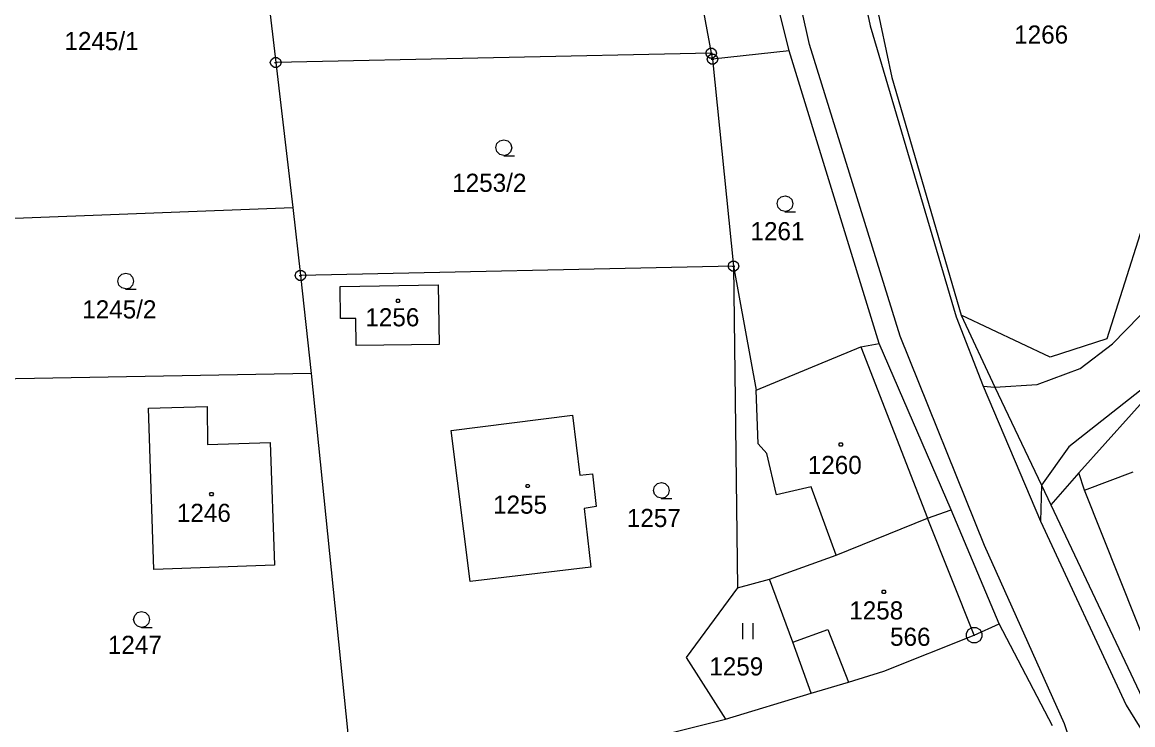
# Model space of a CAD drawing. Extents: x -609861 to -605046, y -1120287 to -1116307.
# Drawn here: x -607182.1 to -607078, y -1118980 to -1118914.2 of the extents above; entities that cross this region are included whole.
import ezdxf

# ---------------------------------------------------------------- set-up
doc = ezdxf.new("R2010")
doc.units = 0
for name, color, linetype in [('Vrstva 1', 7, 'Continuous'), ('Vrstva 2', 7, 'Continuous'), ('Vrstva 3', 7, 'Continuous'), ('Vrstva 4', 7, 'Continuous'), ('Vrstva 5', 7, 'Continuous'), ('Vrstva 8', 7, 'Continuous')]:
    doc.layers.add(name, color=color, linetype=linetype)

msp = doc.modelspace()

# ---------------------------------------------------------------- linework, layer by layer
at = {"layer": 'Vrstva 1'}
for p, q in [((-607055.17, -1118863.8), (-607080.44, -1118943.85)), ((-607109.19, -1118878.4), (-607100.61, -1118919.35)), ((-607124.44, -1118880.49), (-607117.52, -1118917.07)), ((-607161.19, -1118893.61), (-607158.35, -1118917.94)), ((-607110.23, -1118916.83), (-607111.09, -1118913.32)), ((-607117.52, -1118917.07), (-607158.35, -1118917.94)), ((-607117.52, -1118917.07), (-607117.41, -1118917.63)), ((-607110.23, -1118916.83), (-607117.41, -1118917.63)), ((-607101.78, -1118944.28), (-607110.23, -1118916.83)), ((-607158.35, -1118917.94), (-607156.76, -1118931.53)), ((-607117.41, -1118917.63), (-607115.43, -1118937.03)), ((-607100.61, -1118919.35), (-607094.11, -1118941.62)), ((-607188.35, -1118932.73), (-607156.76, -1118931.53)), ((-607156.76, -1118931.53), (-607156.02, -1118937.9)), ((-607115.43, -1118937.03), (-607156.02, -1118937.9)), ((-607115.43, -1118937.03), (-607115.05, -1118967.2)), ((-607115.43, -1118937.03), (-607113.3, -1118948.65)), ((-607156.02, -1118937.9), (-607155.04, -1118947.1)), ((-607152.31, -1118938.95), (-607143.11, -1118938.77)), ((-607152.29, -1118941.95), (-607152.31, -1118938.95)), ((-607143.11, -1118938.77), (-607143.02, -1118944.36)), ((-607150.85, -1118941.93), (-607152.29, -1118941.95)), ((-607150.81, -1118944.48), (-607150.85, -1118941.93)), ((-607085.75, -1118945.56), (-607094.11, -1118941.62)), ((-607094.11, -1118941.62), (-607090.94, -1118948.36)), ((-607143.02, -1118944.36), (-607150.81, -1118944.48)), ((-607103.5, -1118944.58), (-607101.78, -1118944.28)), ((-607095.02, -1118959.89), (-607101.78, -1118944.28)), ((-607080.44, -1118943.85), (-607085.75, -1118945.56)), ((-607071.7, -1118943.74), (-607083.08, -1118956.4)), ((-607113.3, -1118948.65), (-607103.5, -1118944.58)), ((-607155.04, -1118947.1), (-607188.46, -1118947.7)), ((-607155.04, -1118947.1), (-607151.26, -1118984.15)), ((-607090.94, -1118948.36), (-607086.57, -1118957.57)), ((-607170.28, -1118950.35), (-607164.79, -1118950.18)), ((-607169.79, -1118965.48), (-607170.28, -1118950.35)), ((-607164.79, -1118950.18), (-607164.74, -1118953.76)), ((-607141.89, -1118952.43), (-607130.53, -1118951.01)), ((-607130.53, -1118951.01), (-607129.85, -1118956.63)), ((-607140.11, -1118966.61), (-607141.89, -1118952.43)), ((-607164.74, -1118953.76), (-607158.87, -1118953.56)), ((-607158.87, -1118953.56), (-607158.45, -1118965.06)), ((-607129.85, -1118956.63), (-607128.66, -1118956.49)), ((-607128.66, -1118956.49), (-607128.3, -1118959.57)), ((-607083.08, -1118956.4), (-607085.68, -1118959.4)), ((-607082.54, -1118958.04), (-607083.08, -1118956.4)), ((-607082.54, -1118958.04), (-607077.97, -1118956.32)), ((-607086.57, -1118957.57), (-607085.68, -1118959.4)), ((-607075.98, -1118974.5), (-607082.54, -1118958.04)), ((-607128.3, -1118959.57), (-607129.44, -1118959.75)), ((-607129.44, -1118959.75), (-607128.82, -1118965.24)), ((-607097.24, -1118960.65), (-607095.02, -1118959.89)), ((-607090.53, -1118970.56), (-607095.02, -1118959.89)), ((-607085.68, -1118959.4), (-607077.1, -1118977.58)), ((-607105.82, -1118964.13), (-607097.24, -1118960.65)), ((-607112.05, -1118966.38), (-607105.82, -1118964.13)), ((-607158.45, -1118965.06), (-607169.79, -1118965.48)), ((-607128.82, -1118965.24), (-607140.11, -1118966.61)), ((-607115.05, -1118967.2), (-607119.87, -1118973.74)), ((-607115.05, -1118967.2), (-607112.05, -1118966.38)), ((-607109.89, -1118972.29), (-607112.05, -1118966.38)), ((-607092.88, -1118971.63), (-607090.53, -1118970.56)), ((-607085.55, -1118980.13), (-607090.53, -1118970.56)), ((-607108.15, -1118977.08), (-607109.89, -1118972.29)), ((-607101.36, -1118975.02), (-607092.88, -1118971.63)), ((-607119.87, -1118973.74), (-607116.19, -1118979.5)), ((-607104.67, -1118976.04), (-607101.36, -1118975.02)), ((-607108.15, -1118977.08), (-607104.67, -1118976.04)), ((-607116.19, -1118979.5), (-607108.15, -1118977.08)), ((-607126.53, -1118982.11), (-607116.19, -1118979.5))]:
    msp.add_line(p, q, dxfattribs=at)
at = {"layer": 'Vrstva 3'}
for p, q in [((-607114.6, -1118970.49), (-607114.6, -1118971.99)), ((-607113.6, -1118971.99), (-607113.6, -1118970.49))]:
    msp.add_line(p, q, dxfattribs=at)
for points in [[(-607136.96, -1118926.65), (-607137.34, -1118926.55), (-607137.61, -1118926.28), (-607137.71, -1118925.91), (-607137.61, -1118925.54), (-607137.34, -1118925.27), (-607136.97, -1118925.17), (-607136.6, -1118925.27), (-607136.33, -1118925.54), (-607136.23, -1118925.92), (-607136.33, -1118926.3), (-607136.6, -1118926.57), (-607136.98, -1118926.67), (-607135.98, -1118926.67)], [(-607110.6, -1118931.9), (-607110.98, -1118931.8), (-607111.25, -1118931.53), (-607111.35, -1118931.16), (-607111.25, -1118930.79), (-607110.98, -1118930.52), (-607110.61, -1118930.42), (-607110.24, -1118930.52), (-607109.97, -1118930.79), (-607109.87, -1118931.17), (-607109.97, -1118931.55), (-607110.24, -1118931.82), (-607110.62, -1118931.92), (-607109.62, -1118931.92)], [(-607172.4, -1118939.17), (-607172.78, -1118939.07), (-607173.05, -1118938.8), (-607173.15, -1118938.43), (-607173.05, -1118938.06), (-607172.78, -1118937.79), (-607172.41, -1118937.69), (-607172.04, -1118937.79), (-607171.77, -1118938.06), (-607171.67, -1118938.44), (-607171.77, -1118938.82), (-607172.04, -1118939.09), (-607172.42, -1118939.19), (-607171.42, -1118939.19)], [(-607122.19, -1118958.79), (-607122.57, -1118958.69), (-607122.84, -1118958.42), (-607122.94, -1118958.05), (-607122.84, -1118957.68), (-607122.57, -1118957.41), (-607122.2, -1118957.31), (-607121.83, -1118957.41), (-607121.56, -1118957.68), (-607121.46, -1118958.06), (-607121.56, -1118958.44), (-607121.83, -1118958.71), (-607122.21, -1118958.81), (-607121.21, -1118958.81)], [(-607170.92, -1118970.9), (-607171.3, -1118970.8), (-607171.57, -1118970.53), (-607171.67, -1118970.16), (-607171.57, -1118969.79), (-607171.3, -1118969.52), (-607170.93, -1118969.42), (-607170.56, -1118969.52), (-607170.29, -1118969.79), (-607170.19, -1118970.17), (-607170.29, -1118970.55), (-607170.56, -1118970.82), (-607170.94, -1118970.92), (-607169.94, -1118970.92)]]:
    msp.add_lwpolyline(points, dxfattribs=at)
at = {"layer": 'Vrstva 4'}
for p, q in [((-607113.89, -1118861.35), (-607102.64, -1118914.48)), ((-607108.3, -1118916.23), (-607109.02, -1118913.01)), ((-607102.64, -1118914.48), (-607094.56, -1118941.79)), ((-607099.81, -1118943.6), (-607108.3, -1118916.23)), ((-607079.9, -1118944.3), (-607076.09, -1118940.42)), ((-607094.56, -1118941.79), (-607092.05, -1118948.27)), ((-607091.92, -1118963.22), (-607099.81, -1118943.6)), ((-607082.94, -1118946.61), (-607079.9, -1118944.3)), ((-607103.5, -1118944.58), (-607097.24, -1118960.65)), ((-607086.96, -1118948.14), (-607082.94, -1118946.61)), ((-607092.05, -1118948.27), (-607090.94, -1118948.36)), ((-607092.05, -1118948.27), (-607086.67, -1118960.95)), ((-607090.94, -1118948.36), (-607086.96, -1118948.14)), ((-607076.36, -1118947.95), (-607083.99, -1118953.96)), ((-607113.13, -1118953.69), (-607113.3, -1118948.65)), ((-607112.3, -1118954.59), (-607113.13, -1118953.69)), ((-607111.4, -1118958.48), (-607112.3, -1118954.59)), ((-607083.99, -1118953.96), (-607086.57, -1118957.57)), ((-607108.17, -1118957.73), (-607111.4, -1118958.48)), ((-607105.82, -1118964.13), (-607108.17, -1118957.73)), ((-607086.57, -1118957.57), (-607086.67, -1118960.95)), ((-607092.88, -1118971.63), (-607097.24, -1118960.65)), ((-607086.67, -1118960.95), (-607078.63, -1118978.19)), ((-607084.4, -1118979.94), (-607091.92, -1118963.22)), ((-607109.89, -1118972.29), (-607106.59, -1118971.09)), ((-607106.59, -1118971.09), (-607104.67, -1118976.04)), ((-607078.63, -1118978.19), (-607072.92, -1118987.41)), ((-607082.56, -1118985.41), (-607084.4, -1118979.94))]:
    msp.add_line(p, q, dxfattribs=at)
at = {"layer": 'Vrstva 5'}
for points in [[(-607146.8, -1118940.13), (-607146.71, -1118940.28), (-607146.8, -1118940.43), (-607146.98, -1118940.43), (-607147.07, -1118940.28), (-607146.98, -1118940.13)], [(-607105.28, -1118953.61), (-607105.19, -1118953.76), (-607105.28, -1118953.91), (-607105.46, -1118953.91), (-607105.55, -1118953.76), (-607105.46, -1118953.61)], [(-607134.64, -1118957.49), (-607134.55, -1118957.64), (-607134.64, -1118957.79), (-607134.82, -1118957.79), (-607134.91, -1118957.64), (-607134.82, -1118957.49)], [(-607164.28, -1118958.26), (-607164.19, -1118958.41), (-607164.28, -1118958.56), (-607164.46, -1118958.56), (-607164.55, -1118958.41), (-607164.46, -1118958.26)], [(-607101.25, -1118967.41), (-607101.16, -1118967.56), (-607101.25, -1118967.71), (-607101.43, -1118967.71), (-607101.52, -1118967.56), (-607101.43, -1118967.41)]]:
    msp.add_lwpolyline(points, close=True, dxfattribs=at)
at = {"layer": 'Vrstva 8'}
for p, q in [((-607117.64, -1118917.07), (-607117.4, -1118917.07)), ((-607158.47, -1118917.94), (-607158.23, -1118917.94)), ((-607117.53, -1118917.63), (-607117.29, -1118917.63)), ((-607115.55, -1118937.03), (-607115.31, -1118937.03)), ((-607156.14, -1118937.9), (-607155.9, -1118937.9)), ((-607092.93, -1118971.63), (-607092.83, -1118971.63))]:
    msp.add_line(p, q, dxfattribs=at)
for points in [[(-607117.37, -1118916.59), (-607117.12, -1118916.77), (-607117.02, -1118917.06), (-607117.12, -1118917.35), (-607117.37, -1118917.53), (-607117.68, -1118917.53), (-607117.93, -1118917.35), (-607118.03, -1118917.06), (-607117.93, -1118916.77), (-607117.68, -1118916.59)], [(-607117.26, -1118917.15), (-607117.01, -1118917.33), (-607116.91, -1118917.62), (-607117.01, -1118917.91), (-607117.26, -1118918.09), (-607117.57, -1118918.09), (-607117.82, -1118917.91), (-607117.92, -1118917.62), (-607117.82, -1118917.33), (-607117.57, -1118917.15)], [(-607158.2, -1118917.46), (-607157.95, -1118917.64), (-607157.85, -1118917.93), (-607157.95, -1118918.22), (-607158.2, -1118918.4), (-607158.51, -1118918.4), (-607158.76, -1118918.22), (-607158.86, -1118917.93), (-607158.76, -1118917.64), (-607158.51, -1118917.46)], [(-607115.28, -1118936.55), (-607115.03, -1118936.73), (-607114.93, -1118937.02), (-607115.03, -1118937.31), (-607115.28, -1118937.49), (-607115.59, -1118937.49), (-607115.84, -1118937.31), (-607115.94, -1118937.02), (-607115.84, -1118936.73), (-607115.59, -1118936.55)], [(-607155.87, -1118937.42), (-607155.62, -1118937.6), (-607155.52, -1118937.89), (-607155.62, -1118938.18), (-607155.87, -1118938.36), (-607156.18, -1118938.36), (-607156.43, -1118938.18), (-607156.53, -1118937.89), (-607156.43, -1118937.6), (-607156.18, -1118937.42)], [(-607092.69, -1118970.91), (-607092.35, -1118971.1), (-607092.16, -1118971.44), (-607092.16, -1118971.83), (-607092.35, -1118972.17), (-607092.69, -1118972.36), (-607093.08, -1118972.36), (-607093.42, -1118972.17), (-607093.61, -1118971.83), (-607093.61, -1118971.44), (-607093.42, -1118971.1), (-607093.08, -1118970.91)]]:
    msp.add_lwpolyline(points, close=True, dxfattribs=at)

# ---------------------------------------------------------------- texts
at = {"layer": 'Vrstva 2'}
for s, p in [('1245/1', (-607178.157, -1118916.77)), ('1266', (-607089.127, -1118916.16)), ('1253/2', (-607141.806, -1118930.06)), ('1261', (-607113.847, -1118934.6)), ('1245/2', (-607176.487, -1118941.93)), ('1256', (-607149.947, -1118942.67)), ('1260', (-607108.477, -1118956.52)), ('1255', (-607137.977, -1118960.24)), ('1246', (-607167.617, -1118961.01)), ('1257', (-607125.437, -1118961.49)), ('1258', (-607104.587, -1118970.16)), ('1247', (-607174.087, -1118973.39)), ('1259', (-607117.707, -1118975.41))]:
    msp.add_text(s, height=1.7, dxfattribs=at).set_placement(p)
at = {"layer": 'Vrstva 8'}
msp.add_text('566', height=1.7, dxfattribs=at).set_placement((-607100.763, -1118972.63))

doc.saveas('drawing.dxf')
